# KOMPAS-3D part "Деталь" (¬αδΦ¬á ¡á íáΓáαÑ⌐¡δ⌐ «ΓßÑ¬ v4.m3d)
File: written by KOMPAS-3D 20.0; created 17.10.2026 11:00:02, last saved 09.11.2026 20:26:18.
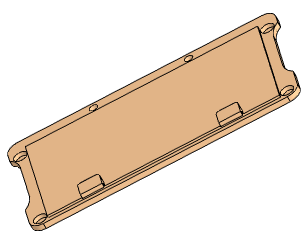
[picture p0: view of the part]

Document properties: Полное имя файла: D:\myProjects\Progect_esp32\box_compas\корпус\крышка на батарейный отсек v4.m3d

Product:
- Part/product: Деталь
    Масса: 0.0866709
  - Body: Тело 2
      Масса: 0.0649966
  - Body: Тело 1
      Масса: 0.0216743

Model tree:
1. Эскиз:1
2. Элемент выдавливания:1
     Расстояние 1 = 0.8
3. Эскиз:2  (with: Элемент выдавливания:1)
4. Элемент выдавливания:2
     Расстояние 1 = 2
5. Эскиз:5  (with: Элемент выдавливания:2)
6. Элемент выдавливания:6
     Расстояние 2 = 2
7. Эскиз:6  (with: Элемент выдавливания:2, Элемент выдавливания:1, Элемент выдавливания:6)
8. Элемент выдавливания:7
     Расстояние 2 = 1.5
9. Массив по сетке:2  (with: Элемент выдавливания:7, Эскиз:6)  (4 pattern instances)
     Шаг 1 = 83; Угол раствора = -90; Шаг 2 = 37
10. Эскиз:8  (with: Элемент выдавливания:2)
11. Элемент выдавливания:8
     Расстояние 2 = 2.8
12. Смещенная плоскость:1  (with: Элемент выдавливания:2)
     Расстояние = -45
13. Зеркальный массив:1
14. Экземпляр ( 1 )
15. Экземпляр ( 2 )  (with: Элемент выдавливания:8)
16. Эскиз:10  (with: Элемент выдавливания:1)
17. Элемент выдавливания:9
     Расстояние 1 = 1.5
18. Эскиз:11  (with: Элемент выдавливания:9, Элемент выдавливания:1)
19. Элемент выдавливания:10
     Расстояние 1 = 1.5
20. Скругление:4  (with: Элемент выдавливания:10)
     Радиус = 1
21. Скругление:6  (with: Элемент выдавливания:9)
     Радиус = 1
22. Скругление:9  (with: Элемент выдавливания:2)
     Радиус = 4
